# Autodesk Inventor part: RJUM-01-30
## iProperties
Author: Malcolm
Shininess: 31.0
PropertySet Name: _Private Model Information
Created: 2001-03
Part Number: RJUM-01-30
Document SubType Name: Modeling
Designer: Malcolm
Description: DryLin Standard Closed
Control State: 0
Master: False
Checked Out: False
PropertySet Name: Design Tracking Control
Density: 0.0
Volumn: 0.0
Area: 0.0
PropertySet Name: Model Information
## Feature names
1. Revolution1
2. Extrusion1
3. Circular Pattern1
4. Extrusion2
5. Revolution2
6. Hole1
7. Chamfer1
8. Revolution3
9. Extrusion3
